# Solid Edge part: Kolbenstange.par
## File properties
Username: bmolnar
Dokumentum tartalom típus: 0
Author: bmolnar
Last saved by: bmolnar
Revision: 85
Sűrűség: 0,000 kg/m^3
Pontosság: 0,990
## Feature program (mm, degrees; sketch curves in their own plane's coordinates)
base feature "unnamed BaseFeature 1"
sketch for "unnamed Protrusion 1" plane through (33.5, 0, 0) normal (1, 0, 0) x-axis (0, 0, 1)
  circle centre (0, 0) radius 40
extrude "unnamed Protrusion 1" add finite 19.5 along +normal
sketch for "Kihúzás_2" plane through (33.5, 0, 0) normal (1, 0, 0) x-axis (0, 0, 1)
  circle centre (0, 0) radius 40
extrude "Kihúzás_2" add finite 4.5 along -normal
sketch for "Furat_1" plane through (-35, 0, 0) normal (-1, 0, 0) x-axis (0, 0, -1)
  hole centre (0, 0) bore radius 5.053
hole "Furat_1" nominal diameter 12 finite  ThreadDepth = 20 mm
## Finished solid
Body 1: solid body, 15 faces, 21 edges, 8 vertices.
  Faces by surface: plane 8, cylinder 4, cone 2, torus 1
  Edges by curve: circle 11, line 6, ellipse 2, intersection 2
Bounding box of the edges (mm; curved faces can reach further): 88.000 x 80.000 x 80.000, from (-35, -40, -40) to (53, 40, 40).
Cylindrical faces by radius (mm): R5.053 x2, R10 x1, R40 x1
Conical faces (half-angle, radius in mm at the cone's reference point): 45 deg R5.553 x1, 59 deg R2.5265 x1
Toroidal faces (ring radius, tube radius in mm): R8.2 r1.8 x1
Planar faces by outward normal: +x 1, +z 1, -x 3, -z 1, oblique 2
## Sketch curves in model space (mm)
circle centre (33.5, 0, 0) radius 40
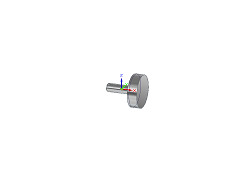
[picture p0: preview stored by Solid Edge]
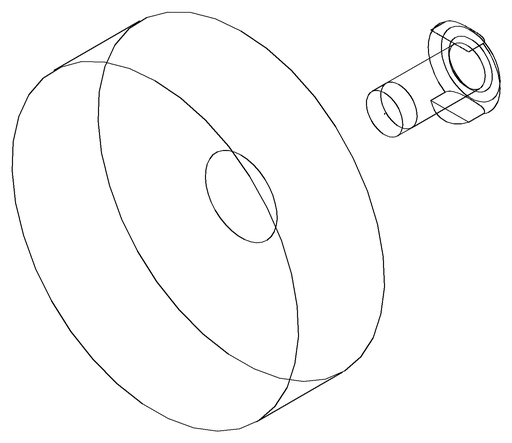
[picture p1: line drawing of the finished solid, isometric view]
